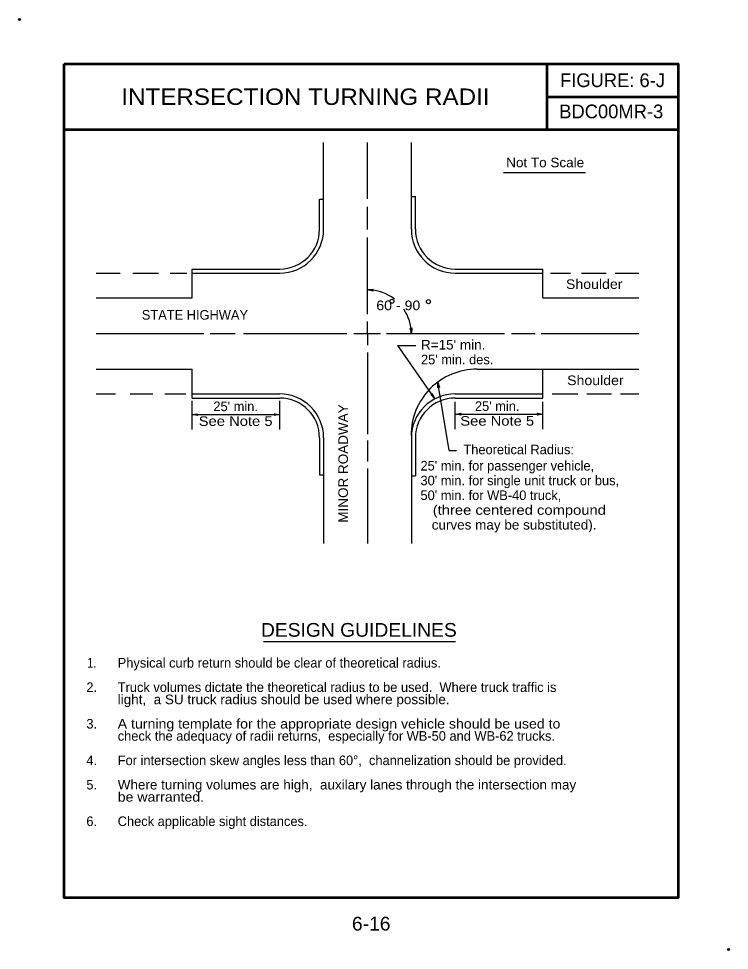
# Model space of a CAD drawing. Extents: x -5.479 to -4.804, y 3.966 to 4.85.
import ezdxf
from ezdxf.enums import TextEntityAlignment as Align

# ---------------------------------------------------------------- set-up
doc = ezdxf.new("R2010")
doc.units = 0
doc.header["$LTSCALE"] = 0.0036
doc.header["$PDMODE"] = 32
doc.header["$PDSIZE"] = 0.0018
doc.linetypes.add('LONG_DASHED', pattern=[7.5, 6, -1.5])
doc.layers.add('1', color=7, linetype='Continuous', lineweight=25)

msp = doc.modelspace()

# ---------------------------------------------------------------- linework, layer by layer
at = {"layer": '1', "lineweight": 53}
for p, q in [((-4.977792, 4.80765), (-4.977792, 4.74515)), ((-4.977792, 4.7764), (-4.852792, 4.7764)), ((-5.436125, 4.74515), (-4.852792, 4.74515))]:
    msp.add_line(p, q, dxfattribs=at)
at = {"layer": '1'}
for p, q in [((-5.189683, 4.650592), (-5.189683, 4.7328)), ((-5.148017, 4.679525), (-5.148017, 4.7328)), ((-5.10635, 4.650592), (-5.10635, 4.7328)), ((-5.018717, 4.704408), (-4.94085, 4.704408)), ((-5.193592, 4.650592), (-5.193592, 4.679092)), ((-5.193592, 4.679092), (-5.1898, 4.679092)), ((-5.106225, 4.681642), (-5.10245, 4.681642)), ((-5.10245, 4.650592), (-5.10245, 4.681692)), ((-5.148017, 4.650508), (-5.148017, 4.671733)), ((-5.148017, 4.569942), (-5.148017, 4.642717)), ((-5.405683, 4.608925), (-5.382967, 4.608925)), ((-5.370842, 4.608925), (-5.346592, 4.608925)), ((-5.335333, 4.608925), (-5.31975, 4.608925)), ((-5.314683, 4.585483), (-5.314683, 4.612825)), ((-5.314683, 4.612825), (-5.23135, 4.612825)), ((-5.314683, 4.608925), (-5.23135, 4.608925)), ((-5.064683, 4.612825), (-4.98135, 4.612825)), ((-5.064683, 4.608925), (-4.98135, 4.608925)), ((-4.98135, 4.585483), (-4.98135, 4.612825)), ((-4.974208, 4.608925), (-4.955158, 4.608925)), ((-4.944758, 4.608925), (-4.921383, 4.608925)), ((-4.912717, 4.608925), (-4.890342, 4.608925)), ((-5.147925, 4.593133), (-5.142542, 4.593608)), ((-5.405683, 4.585483), (-5.314683, 4.585483)), ((-4.98135, 4.585483), (-4.890342, 4.585483)), ((-5.148017, 4.551633), (-5.148017, 4.563017)), ((-5.106225, 4.55155), (-5.107467, 4.556808)), ((-5.405683, 4.551633), (-5.3035, 4.551633)), ((-5.297433, 4.551633), (-5.273625, 4.551633)), ((-5.265833, 4.551633), (-5.167542, 4.551633)), ((-5.161042, 4.551633), (-5.1355, 4.551633)), ((-5.148017, 4.551633), (-5.148017, 4.540483)), ((-5.129867, 4.551633), (-5.017717, 4.551633)), ((-5.011225, 4.551633), (-4.988708, 4.551633)), ((-4.983083, 4.551633), (-4.890342, 4.551633)), ((-5.119492, 4.540192), (-5.0846, 4.490367)), ((-5.119492, 4.540192), (-5.102133, 4.540192)), ((-5.148017, 4.533558), (-5.148017, 4.456025)), ((-5.405683, 4.517775), (-5.314683, 4.517775)), ((-5.314683, 4.490433), (-5.314683, 4.517775)), ((-4.98135, 4.517775), (-4.890342, 4.517775)), ((-4.98135, 4.490433), (-4.98135, 4.517775)), ((-5.070283, 4.44065), (-5.081117, 4.505583)), ((-5.081117, 4.505558), (-5.079458, 4.500417)), ((-5.405683, 4.494342), (-5.387292, 4.494342)), ((-5.373433, 4.494342), (-5.351792, 4.494342)), ((-5.340533, 4.494342), (-5.320617, 4.494342)), ((-5.314683, 4.494342), (-5.23135, 4.494342)), ((-5.084158, 4.489683), (-5.08785, 4.493617)), ((-5.064683, 4.494342), (-4.98135, 4.494342)), ((-4.972475, 4.494342), (-4.948225, 4.494342)), ((-4.939575, 4.494342), (-4.916183, 4.494342)), ((-4.907533, 4.494342), (-4.890342, 4.494342)), ((-5.314683, 4.490433), (-5.23135, 4.490433)), ((-5.314683, 4.460567), (-5.314683, 4.487858)), ((-5.23135, 4.460567), (-5.23135, 4.487858)), ((-5.064683, 4.490433), (-4.98135, 4.490433)), ((-5.064683, 4.461008), (-5.064683, 4.486733)), ((-4.98135, 4.461008), (-4.98135, 4.48695)), ((-5.314758, 4.47465), (-5.2313, 4.47465)), ((-5.314683, 4.474717), (-5.309333, 4.475508)), ((-5.23145, 4.4747), (-5.2368, 4.473908)), ((-5.064533, 4.47515), (-5.059175, 4.475942)), ((-5.06405, 4.475075), (-4.981925, 4.475075)), ((-4.98145, 4.475092), (-4.9868, 4.4743)), ((-5.193592, 4.452675), (-5.193592, 4.417475)), ((-5.189683, 4.452675), (-5.189683, 4.352492)), ((-5.148017, 4.449967), (-5.148017, 4.430033)), ((-5.10635, 4.452675), (-5.10635, 4.352492)), ((-5.10245, 4.452675), (-5.10245, 4.416725)), ((-5.070283, 4.44065), (-5.063408, 4.44065)), ((-5.148017, 4.423533), (-5.148017, 4.352492)), ((-5.193592, 4.417475), (-5.18975, 4.417475)), ((-5.106392, 4.416725), (-5.10245, 4.416725)), ((-5.2468, 4.259192), (-5.064267, 4.259192))]:
    msp.add_line(p, q, dxfattribs=at)
at = {"layer": '1', "linetype": 'LONG_DASHED'}
msp.add_line((-5.04385, 4.517775), (-4.98135, 4.517775), dxfattribs=at)
at = {"layer": '1', "lineweight": 53}
msp.add_lwpolyline([(-5.436125, 4.80765), (-4.852792, 4.80765), (-4.852792, 4.015983), (-5.436125, 4.015983)], close=True, dxfattribs=at)
at = {"layer": '1'}
for points in [[(-5.143492, 4.592883), (-5.1425, 4.591967), (-5.147992, 4.59315)], [(-5.142533, 4.593592), (-5.143492, 4.5929), (-5.143492, 4.592883)], [(-5.10745, 4.556825), (-5.106633, 4.555975), (-5.106617, 4.555975)], [(-5.106617, 4.555975), (-5.105842, 4.557092), (-5.106225, 4.551483)], [(-5.080383, 4.501175), (-5.081067, 4.500017), (-5.081117, 4.505617)], [(-5.079483, 4.500392), (-5.08035, 4.501183), (-5.080383, 4.501175)], [(-5.087842, 4.493642), (-5.086708, 4.493317), (-5.0867, 4.493325)], [(-5.0867, 4.493325), (-5.086583, 4.494683), (-5.084125, 4.489608)], [(-5.310242, 4.474725), (-5.3092, 4.473858), (-5.31475, 4.474725)], [(-5.309325, 4.475483), (-5.310242, 4.474742), (-5.310242, 4.474725)], [(-5.235892, 4.474692), (-5.236933, 4.475558), (-5.231383, 4.474692)], [(-5.236808, 4.473933), (-5.235892, 4.474675), (-5.235892, 4.474692)], [(-5.060083, 4.475158), (-5.059042, 4.4743), (-5.064592, 4.475158)], [(-5.059167, 4.475925), (-5.060083, 4.475183), (-5.060083, 4.475158)], [(-4.985892, 4.475075), (-4.986933, 4.475942), (-4.981383, 4.475075)], [(-4.986808, 4.474317), (-4.985892, 4.475058), (-4.985892, 4.475075)]]:
    msp.add_lwpolyline(points, dxfattribs=at)
for centre in [(-5.124842, 4.582225), (-5.090117, 4.581875)]:
    msp.add_circle(centre, 0.001913, dxfattribs=at)
for centre, radius, start, end in [((-5.231352, 4.650588), 0.041667, 270, 0), ((-5.231352, 4.650588), 0.03776, 270, 0), ((-5.064685, 4.650588), 0.041667, 180, 270), ((-5.043852, 4.580275), 0.0625, 270, 270), ((-5.043852, 4.580275), 0.0625, 270, 270), ((-5.064685, 4.650588), 0.03776, 180, 270), ((-5.148071, 4.551452), 0.041667, 52.0846, 90), ((-5.148071, 4.551452), 0.041667, 0.24351, 33.83329), ((-5.043852, 4.455275), 0.0625, 90, 90), ((-5.043852, 4.455275), 0.0625, 90, 90), ((-5.043852, 4.455275), 0.0625, 90, 90), ((-5.043852, 4.455275), 0.0625, 90, 90), ((-5.043852, 4.455275), 0.0625, 90, 90), ((-5.043852, 4.455275), 0.0625, 90, 90), ((-5.043852, 4.455275), 0.0625, 90, 90), ((-5.043852, 4.455275), 0.0625, 90, 90), ((-5.043852, 4.455275), 0.0625, 90, 90), ((-5.043852, 4.455275), 0.0625, 90, 90), ((-5.231352, 4.452671), 0.041667, 0, 90), ((-5.064685, 4.452671), 0.041667, 90, 180), ((-5.231352, 4.452671), 0.03776, 0, 90), ((-5.064685, 4.452671), 0.03776, 90, 180), ((-4.952675, 4.385994), 0.0625, 270, 270), ((-5.043852, 4.356838), 0.0625, 180, 180), ((-5.043852, 4.356838), 0.0625, 180, 180), ((-4.952675, 4.260994), 0.0625, 90, 90)]:
    msp.add_arc(centre, radius, start, end, dxfattribs=at)
at = {"layer": '1', "linetype": 'LONG_DASHED'}
msp.add_arc((-5.044102, 4.455254), 0.0625, 89.81602, 180.37382, dxfattribs=at)
at = {"layer": '1'}
for p in [(-5.478492, 4.8496), (-4.805158, 3.9671)]:
    msp.add_point(p, dxfattribs=at)

# ---------------------------------------------------------------- texts
for s, height, p in [('FIGURE: 6-J', 0.01303, (-4.915296, 4.785508)), ('BDC00MR-3', 0.01303, (-4.916479, 4.755908)), ("25' min.", 0.009117, (-5.273242, 4.477967)), ("25' min.", 0.009117, (-5.0248, 4.478175)), ('Theoretical Radius:', 0.009117, (-5.004404, 4.437)), ('2.', 0.009117, (-5.409958, 4.211425)), ('3.', 0.009117, (-5.409958, 4.176725)), ('4.', 0.009117, (-5.409958, 4.142025)), ('5.', 0.009117, (-5.409958, 4.118892)), ('6.', 0.009117, (-5.409958, 4.084192))]:
    msp.add_text(s, height=height, dxfattribs=at).set_placement(p, align=Align.CENTER)
for s, height, width, p in [('INTERSECTION TURNING RADII', 0.01562, 1.1, (-5.206958, 4.768583)), ('Not To Scale', 0.009117, 1.05, (-4.979229, 4.7094)), ('Shoulder', 0.009117, 1.1, (-4.932642, 4.593967)), ('60 - 90', 0.009117, 1.1, (-5.118742, 4.573808)), ('Shoulder', 0.009117, 1.1, (-4.931525, 4.502667)), ('See Note 5', 0.009117, 1.15, (-5.273246, 4.46395)), ('See Note 5', 0.009117, 1.15, (-5.024804, 4.464158)), ('DESIGN GUIDELINES', 0.01303, 1.05, (-5.156188, 4.26385)), ('1.', 0.009117, 0.85, (-5.409958, 4.234558)), ('6-16', 0.01303, 1.05, (-5.144463, 3.985025))]:
    msp.add_text(s, height=height, dxfattribs=dict(at, width=width)).set_placement(p, align=Align.CENTER)
for s, p in [('STATE HIGHWAY', (-5.362383, 4.5648)), ("25' min. des.", (-5.097192, 4.522442)), ("25' min. for passenger vehicle,", (-5.097675, 4.421625)), ("30' min. for single unit truck or bus,", (-5.097675, 4.407608)), ("50' min. for WB-40 truck,", (-5.097675, 4.393592)), ('Physical curb return should be clear of theoretical radius.', (-5.385258, 4.234558)), ('Truck volumes dictate the theoretical radius to be used.  Where truck traffic is', (-5.385258, 4.211425)), ('check the adequacy of radii returns,  especially for WB-50 and WB-62 trucks.', (-5.385258, 4.165158)), ('For intersection skew angles less than 60°,  channelization should be provided.', (-5.385258, 4.142025)), ('Check applicable sight distances.', (-5.385258, 4.084192))]:
    msp.add_text(s, height=0.009117, dxfattribs=at).set_placement(p)
for s, width, p in [("R=15' min.", 1.05, (-5.097192, 4.536458)), ('   (three centered compound', 1.15, (-5.097675, 4.379575)), ('   curves may be substituted).', 1.05, (-5.097675, 4.365558)), ('light,  a SU truck radius should be used where possible.', 1.05, (-5.385258, 4.199858)), ('A turning template for the appropriate design vehicle should be used to', 1.1, (-5.385258, 4.176725)), ('Where turning volumes are high,  auxilary lanes through the intersection may', 1.05, (-5.385258, 4.118892)), ('be warranted.', 1.1, (-5.385258, 4.107325))]:
    msp.add_text(s, height=0.009117, dxfattribs=dict(at, width=width)).set_placement(p)
at = {"layer": '1', "width": 1.05}
msp.add_text('MINOR ROADWAY', height=0.009117, rotation=90, dxfattribs=at).set_placement((-5.166583, 4.372092))

doc.saveas('drawing.dxf')
